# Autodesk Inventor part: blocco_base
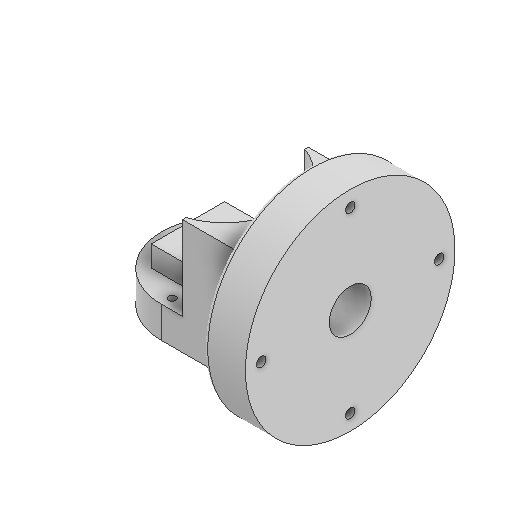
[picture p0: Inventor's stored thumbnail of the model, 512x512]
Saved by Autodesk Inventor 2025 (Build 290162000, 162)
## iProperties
Created: 2025-06
Part Number: blocco_base
Material: Generico
Document SubType Name: Modeling
Designer: Ryzen5700u
Density: 1 g/cm^3
Appearance: Default
Author: Ryzen5700u
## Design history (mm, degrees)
sketch "Schizzo1"
  geometry: L1 (17.5, -17.5)-(-17.5, -17.5); L2 (-17.5, -17.5)-(-17.5, 17.5); L3 (-17.5, 17.5)-(17.5, 17.5); L4 (17.5, 17.5)-(17.5, -17.5); L5 (17.5, -17.5)-(-17.5, 17.5); L6 (-17.5, -17.5)-(17.5, 17.5); C1 r 10 at (0, 0); 1 further point
  constraints: 12 end point, 2 midpoint, 2 parallel, 1 centre point, 1 coincident, 1 horizontal, 1 perpendicular
  dimensions: "d0" = 35 distance of L2.end L3.end; "d1" = 35 distance of L1.end L2.end; "d14" = 20 diameter of C1
extrude "Estrusione1" new body sketch "Schizzo1" distance "d2" = 10; taper "d3" = 0 deg
sketch "Schizzo2"
  geometry: C1 r 30 at (0, 0); C2 r 10 at (0, 0); 1 further point
  constraints: 2 centre point, 2 coincident
  dimensions: "d6" = 60 diameter of C1; "d13" = 20 diameter of C2
extrude "Estrusione2" join sketch "Schizzo2" distance "d4" = 15; taper "d5" = 0 deg
sketch "Schizzo3"
  geometry: L1 (-40, -30)-(40, -30); L2 (40, -30)-(40, 30); L3 (40, 30)-(-40, 30); L4 (-40, 30)-(-40, -30); L5 (-40, -30)-(40, 30); L6 (40, -30)-(-40, 30); L7 (0, -30)-(0, 30); C1 r 30 at (0, 0) reference; 3 further points
  constraints: 14 end point, 4 midpoint, 2 parallel, 1 horizontal, 1 perpendicular
  dimensions: "d7" = 80 distance of L3.end L2.end; "d8" = 60 distance of L2.end L1.end
node "Piano di lavoro1"
extrude "Estrusione3" join sketch "Schizzo3" stored distance "d9" = 10; taper "d10" = 0 deg
sketch "Schizzo4"
  geometry: L1 (0, 0)-(0, 55) reference; L2 (60, 55)-(0, 55) reference; C1 r 50 at (30, 27.5); C2 r 15 at (30, 27.5); 1 further point
  constraints: 2 centre point, 1 coincident
  dimensions: "d19" = 100 diameter of C1; "d36" = 30 diameter of C2
extrude "Estrusione4" join sketch "Schizzo4" distance "d11" = 20; taper "d12" = 0 deg
chamfer "Smusso1" distance "d15" = 10; stored, may be unused: second distance "d16" = 2, angle "d17" = 45 deg
fillet "Raccordo2" dims "d20" = 5
sketch "Schizzo5"
  geometry: A1 r 42.5 centre (0, 0) between (-42.5, 0) and (0, 42.5); 3 further points
  constraints: 4 point on circle, 1 centre point
  dimensions: "d21" = 85 diameter of A1
hole "Foro1" sketch "Schizzo5" at (-42.5, 0), (0, 42.5), (42.5, 0), (0, -42.5) diameter "d22" = 4.5; stored, may be unused: countersink angle "d26" = 90 deg, drill point angle "d28" = 0 deg; dims "d23" = 6, "d24" = 8, "d25" = 4.6, "d27" = 50
sketch "Schizzo6"
  geometry: C1 r 3 at (-25, 0) reference; C2 r 3 at (0, 25) reference; C3 r 3 at (0, -25) reference; C4 r 3 at (25, 0) reference; 1 further point
hole "Foro2" sketch "Schizzo6" at (-25, 0), (0, -25), (25, 0), (0, 25) diameter "d29" = 3.4; stored, may be unused: countersink angle "d33" = 90 deg, drill point angle "d35" = 0 deg; dims "d30" = 6, "d31" = 6.5, "d32" = 3.4, "d34" = 50
sketch "Schizzo7"
  geometry: C1 r 50 at (0, 0) reference; 2 further points
  constraints: 1 coincident
hole "Foro3" sketch "Schizzo7" at (0, 0) diameter "d37" = 20; stored, may be unused: countersink angle "d41" = 90 deg, drill point angle "d43" = 0 deg; dims "d38" = 6, "d39" = 6.5, "d40" = 3.4, "d42" = 50
fillet "Raccordo3" dims "d44" = 2
node "Solido1"
node "Riferimento1"
node "Riferimento2"
node "Riferimento3"
node "Riferimento4"
